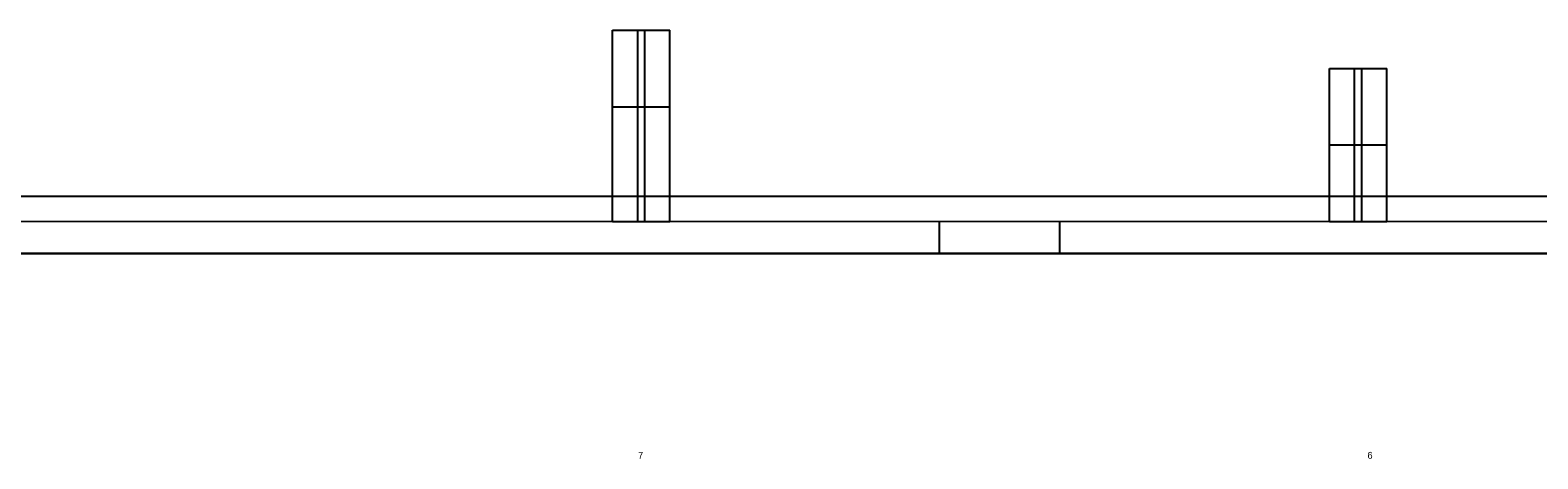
# Model space of a CAD drawing. Extents: x 49991 to 50160, y 49948 to 50051.
# Drawn here: x 50068 to 50081.14, y 50019.63 to 50023.37 of the extents above; entities that cross this region are included whole.
import ezdxf

# ---------------------------------------------------------------- set-up
doc = ezdxf.new("R2010")
doc.units = 0
for name, color, linetype in [('Level 1', 7, 'Continuous'), ('Level 3', 7, 'Continuous'), ('Level 4', 7, 'Continuous')]:
    doc.layers.add(name, color=color, linetype=linetype)

msp = doc.modelspace()

# ---------------------------------------------------------------- linework, layer by layer
at = {"layer": 'Level 1'}
for p, q in [((50073.077, 50022.702), (50073.077, 50023.369)), ((50073.077, 50023.369), (50073.577, 50023.369)), ((50073.577, 50022.702), (50073.577, 50023.369)), ((50079.327, 50022.369), (50079.327, 50023.035)), ((50079.327, 50023.035), (50079.827, 50023.035)), ((50079.827, 50022.369), (50079.827, 50023.035)), ((50073.077, 50021.702), (50073.077, 50022.702)), ((50073.077, 50022.702), (50073.577, 50022.702)), ((50073.077, 50022.702), (50073.577, 50022.702)), ((50073.577, 50021.702), (50073.577, 50022.702)), ((50079.327, 50021.702), (50079.327, 50022.369)), ((50079.327, 50022.369), (50079.827, 50022.369)), ((50079.327, 50022.369), (50079.827, 50022.369)), ((50079.827, 50021.702), (50079.827, 50022.369)), ((50067.327, 50021.922), (50073.077, 50021.922)), ((50073.577, 50021.922), (50079.327, 50021.922)), ((50079.827, 50021.922), (50085.577, 50021.922)), ((50034.505, 50021.704), (50093.827, 50021.702)), ((50073.077, 50021.702), (50073.577, 50021.702)), ((50075.927, 50021.422), (50075.927, 50021.702)), ((50079.327, 50021.702), (50079.827, 50021.702)), ((50038.232, 50021.423), (50093.827, 50021.42))]:
    msp.add_line(p, q, dxfattribs=at)
at = {"layer": 'Level 3'}
for p, q in [((50073.327, 50021.422), (50067.077, 50021.422)), ((50079.577, 50021.422), (50073.327, 50021.422)), ((50085.827, 50021.422), (50079.577, 50021.422))]:
    msp.add_line(p, q, dxfattribs=at)
at = {"layer": 'Level 4'}
for p, q in [((50073.296, 50022.702), (50073.296, 50023.369)), ((50073.358, 50022.702), (50073.358, 50023.369)), ((50079.546, 50022.369), (50079.546, 50023.035)), ((50079.608, 50022.369), (50079.608, 50023.035)), ((50073.296, 50021.702), (50073.296, 50022.702)), ((50073.358, 50021.702), (50073.358, 50022.702)), ((50079.546, 50021.702), (50079.546, 50022.369)), ((50079.608, 50021.702), (50079.608, 50022.369)), ((50073.077, 50021.922), (50073.577, 50021.922)), ((50079.327, 50021.922), (50079.827, 50021.922)), ((50076.977, 50021.422), (50076.977, 50021.702))]:
    msp.add_line(p, q, dxfattribs=at)

# ---------------------------------------------------------------- texts
at = {"layer": 'Level 3'}
for s, p in [('7', (50073.299, 50019.633)), ('6', (50079.658, 50019.633))]:
    msp.add_text(s, height=0.06, dxfattribs=at).set_placement(p)

doc.saveas('drawing.dxf')
